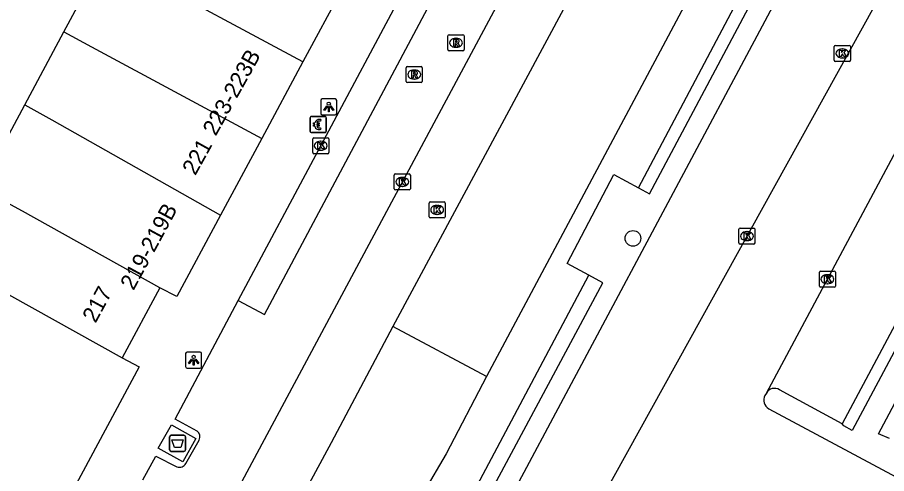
# Model space of a CAD drawing. Extents: x 159489 to 160304, y 383826 to 384530.
# Drawn here: x 159796 to 159850, y 384031.5 to 384059.8 of the extents above; entities that cross this region are included whole.
import ezdxf

# ---------------------------------------------------------------- set-up
doc = ezdxf.new("R2010")
doc.units = 0
for name, color, linetype in [('IMGEO_Afval_apart_plaats', 7, 'Continuous'), ('IMGEO_Betaalautomaat', 7, 'Continuous'), ('IMGEO_Boom', 7, 'Continuous'), ('IMGEO_Haag', 7, 'Continuous'), ('IMGEO_Kolk', 7, 'Continuous'), ('IMGEO_Lichtpunt', 7, 'Continuous'), ('IMGEO_OVBaan_gesloten', 7, 'Continuous'), ('IMGEO_Pand', 7, 'Continuous'), ('IMGEO_Pand_nummerreeks', 7, 'Continuous'), ('IMGEO_Parkeervlak_open', 7, 'Continuous'), ('IMGEO_Rijbaan_lokaal_gesloten', 7, 'Continuous'), ('IMGEO_Rijbaan_lokaal_open', 7, 'Continuous'), ('IMGEO_Rioolput', 7, 'Continuous'), ('IMGEO_Voetpad_gesloten', 7, 'Continuous'), ('IMGEO_Voetpad_open', 7, 'Continuous')]:
    doc.layers.add(name, color=color, linetype=linetype)

msp = doc.modelspace()

# ---------------------------------------------------------------- linework, layer by layer
at = {"layer": 'IMGEO_Afval_apart_plaats'}
for p, q in [((159805.424, 384032.955), (159805.424, 384033.755)), ((159805.424, 384033.755), (159805.424, 384032.955)), ((159805.524, 384033.855), (159806.314, 384033.855)), ((159806.314, 384033.855), (159805.524, 384033.855)), ((159806.414, 384033.755), (159806.414, 384032.955)), ((159806.414, 384032.955), (159806.414, 384033.755)), ((159806.314, 384032.855), (159805.524, 384032.855)), ((159805.524, 384032.855), (159806.314, 384032.855))]:
    msp.add_line(p, q, dxfattribs=at)
msp.add_lwpolyline([(159805.567, 384033.569), (159806.271, 384033.569), (159806.122, 384033.099), (159805.716, 384033.099), (159805.567, 384033.569)], dxfattribs=at)
for centre, start, end in [((159805.524, 384033.755), 90, 180), ((159805.524, 384033.755), 90, 180), ((159806.314, 384033.755), 0, 90), ((159806.314, 384033.755), 360, 90), ((159805.524, 384032.955), 180, 270), ((159805.524, 384032.955), 180, 270), ((159806.314, 384032.955), 270, 0), ((159806.314, 384032.955), 270, 0)]:
    msp.add_arc(centre, 0.1, start, end, dxfattribs=at)
at = {"layer": 'IMGEO_Betaalautomaat'}
for p, q in [((159814.162, 384052.733), (159814.162, 384053.574)), ((159814.162, 384053.574), (159814.162, 384052.733)), ((159814.237, 384053.657), (159815.078, 384053.657)), ((159815.078, 384053.657), (159814.237, 384053.657)), ((159814.824, 384053.462), (159814.807, 384053.362)), ((159815.161, 384053.583), (159815.161, 384052.742)), ((159815.161, 384052.742), (159815.161, 384053.583)), ((159814.445, 384053.121), (159814.445, 384053.189)), ((159814.566, 384053.189), (159814.566, 384053.121)), ((159814.811, 384052.956), (159814.833, 384052.869)), ((159815.087, 384052.658), (159814.246, 384052.658)), ((159814.246, 384052.658), (159815.087, 384052.658))]:
    msp.add_line(p, q, dxfattribs=at)
for points in [[(159814.445, 384053.189), (159814.376, 384053.189), (159814.376, 384053.258), (159814.455, 384053.258)], [(159814.45, 384053.052), (159814.376, 384053.052), (159814.376, 384053.121), (159814.445, 384053.121)], [(159814.577, 384053.258), (159814.724, 384053.258), (159814.724, 384053.189), (159814.566, 384053.189)], [(159814.566, 384053.121), (159814.724, 384053.121), (159814.724, 384053.052), (159814.58, 384053.052)]]:
    msp.add_lwpolyline(points, dxfattribs=at)
for centre, radius, start, end in [((159814.24, 384053.58), 0.0779, 92.4484, 184.2845), ((159814.24, 384053.58), 0.0779, 92.4484, 184.2845), ((159814.738, 384053.182), 0.293, 73.014, 165.0139), ((159814.744, 384053.195), 0.179, 69.3236, 159.5683), ((159815.084, 384053.58), 0.0779, 2.4484, 94.2845), ((159815.084, 384053.58), 0.0779, 2.4484, 94.2845), ((159814.711, 384053.107), 0.267, 191.8096, 297.0389), ((159814.744, 384053.122), 0.179, 202.7625, 291.8693), ((159814.24, 384052.736), 0.0779, 182.4484, 274.2845), ((159814.24, 384052.736), 0.0779, 182.4484, 274.2845), ((159815.084, 384052.736), 0.0779, 272.4484, 4.2845), ((159815.084, 384052.736), 0.0779, 272.4484, 4.2845)]:
    msp.add_arc(centre, radius, start, end, dxfattribs=at)
at = {"layer": 'IMGEO_Boom'}
msp.add_circle((159834.227, 384046.085), 0.489, dxfattribs=at)
at = {"layer": 'IMGEO_Haag'}
for points in [[(159834.573, 384049.218), (159855.048, 384087.89)], [(159868.118, 384073.693), (159868.262, 384073.615), (159868.311, 384073.703), (159868.832, 384073.417), (159847.849, 384034.159), (159847.33, 384034.432), (159847.224, 384034.568)], [(159850.179, 384033.662), (159849.485, 384033.948), (159870.159, 384072.714), (159870.692, 384072.419), (159870.643, 384072.32), (159870.785, 384072.243)], [(159814.597, 384012.024), (159831.482, 384043.804)]]:
    msp.add_lwpolyline(points, dxfattribs=at)
at = {"layer": 'IMGEO_Kolk'}
for p, q in [((159846.742, 384057.151), (159846.742, 384058.003)), ((159846.817, 384058.077), (159847.669, 384058.077)), ((159847.23, 384057.857), (159847.255, 384057.857)), ((159847.743, 384058.003), (159847.743, 384057.151)), ((159847.253, 384057.297), (159847.228, 384057.297)), ((159847.669, 384057.077), (159846.817, 384057.077)), ((159814.392, 384052.341), (159815.244, 384052.341)), ((159814.317, 384051.415), (159814.317, 384052.267)), ((159814.805, 384052.121), (159814.83, 384052.121)), ((159815.318, 384052.267), (159815.318, 384051.415)), ((159815.244, 384051.341), (159814.392, 384051.341)), ((159814.828, 384051.561), (159814.803, 384051.561)), ((159819.387, 384049.169), (159819.387, 384050.021)), ((159819.462, 384050.095), (159820.314, 384050.095)), ((159819.875, 384049.875), (159819.9, 384049.875)), ((159820.388, 384050.021), (159820.388, 384049.169)), ((159820.314, 384049.095), (159819.462, 384049.095)), ((159819.898, 384049.315), (159819.873, 384049.315)), ((159821.553, 384047.43), (159821.553, 384048.282)), ((159821.628, 384048.356), (159822.48, 384048.356)), ((159822.041, 384048.136), (159822.066, 384048.136)), ((159822.554, 384048.282), (159822.554, 384047.43)), ((159822.064, 384047.576), (159822.039, 384047.576)), ((159822.48, 384047.356), (159821.628, 384047.356)), ((159840.813, 384045.8), (159840.813, 384046.652)), ((159840.888, 384046.726), (159841.74, 384046.726)), ((159841.301, 384046.506), (159841.326, 384046.506)), ((159841.814, 384046.652), (159841.814, 384045.8)), ((159841.324, 384045.946), (159841.299, 384045.946)), ((159841.74, 384045.726), (159840.888, 384045.726)), ((159845.815, 384043.125), (159845.815, 384043.977)), ((159845.89, 384044.051), (159846.742, 384044.051)), ((159846.303, 384043.831), (159846.328, 384043.831)), ((159846.816, 384043.977), (159846.816, 384043.125)), ((159846.326, 384043.271), (159846.301, 384043.271)), ((159846.742, 384043.051), (159845.89, 384043.051))]:
    msp.add_line(p, q, dxfattribs=at)
for points in [[(159846.742, 384057.151), (159846.742, 384058.003)], [(159846.817, 384058.077), (159847.669, 384058.077)], [(159847.063, 384057.777), (159847.186, 384057.777), (159847.186, 384057.626), (159847.316, 384057.777), (159847.48, 384057.777), (159847.334, 384057.626), (159847.487, 384057.377), (159847.335, 384057.377), (159847.25, 384057.541), (159847.186, 384057.474), (159847.186, 384057.377), (159847.063, 384057.377), (159847.063, 384057.777)], [(159847.743, 384058.003), (159847.743, 384057.151)], [(159847.669, 384057.077), (159846.817, 384057.077)], [(159814.392, 384052.341), (159815.244, 384052.341)], [(159814.317, 384051.415), (159814.317, 384052.267)], [(159814.638, 384052.041), (159814.761, 384052.041), (159814.761, 384051.89), (159814.891, 384052.041), (159815.055, 384052.041), (159814.909, 384051.89), (159815.062, 384051.641), (159814.91, 384051.641), (159814.825, 384051.805), (159814.761, 384051.738), (159814.761, 384051.641), (159814.638, 384051.641), (159814.638, 384052.041)], [(159815.318, 384052.267), (159815.318, 384051.415)], [(159815.244, 384051.341), (159814.392, 384051.341)], [(159819.387, 384049.169), (159819.387, 384050.021)], [(159819.462, 384050.095), (159820.314, 384050.095)], [(159819.708, 384049.795), (159819.831, 384049.795), (159819.831, 384049.644), (159819.961, 384049.795), (159820.125, 384049.795), (159819.979, 384049.644), (159820.132, 384049.395), (159819.98, 384049.395), (159819.895, 384049.559), (159819.831, 384049.492), (159819.831, 384049.395), (159819.708, 384049.395), (159819.708, 384049.795)], [(159820.388, 384050.021), (159820.388, 384049.169)], [(159820.314, 384049.095), (159819.462, 384049.095)], [(159821.553, 384047.43), (159821.553, 384048.282)], [(159821.628, 384048.356), (159822.48, 384048.356)], [(159821.874, 384048.056), (159821.997, 384048.056), (159821.997, 384047.905), (159822.127, 384048.056), (159822.291, 384048.056), (159822.145, 384047.905), (159822.298, 384047.656), (159822.146, 384047.656), (159822.061, 384047.82), (159821.997, 384047.753), (159821.997, 384047.656), (159821.874, 384047.656), (159821.874, 384048.056)], [(159822.554, 384048.282), (159822.554, 384047.43)], [(159822.48, 384047.356), (159821.628, 384047.356)], [(159840.813, 384045.8), (159840.813, 384046.652)], [(159840.888, 384046.726), (159841.74, 384046.726)], [(159841.134, 384046.426), (159841.257, 384046.426), (159841.257, 384046.275), (159841.387, 384046.426), (159841.551, 384046.426), (159841.405, 384046.275), (159841.558, 384046.026), (159841.406, 384046.026), (159841.321, 384046.19), (159841.257, 384046.123), (159841.257, 384046.026), (159841.134, 384046.026), (159841.134, 384046.426)], [(159841.814, 384046.652), (159841.814, 384045.8)], [(159841.74, 384045.726), (159840.888, 384045.726)], [(159845.815, 384043.125), (159845.815, 384043.977)], [(159845.89, 384044.051), (159846.742, 384044.051)], [(159846.136, 384043.751), (159846.259, 384043.751), (159846.259, 384043.6), (159846.389, 384043.751), (159846.553, 384043.751), (159846.407, 384043.6), (159846.56, 384043.351), (159846.408, 384043.351), (159846.323, 384043.515), (159846.259, 384043.448), (159846.259, 384043.351), (159846.136, 384043.351), (159846.136, 384043.751)], [(159846.816, 384043.977), (159846.816, 384043.125)], [(159846.742, 384043.051), (159845.89, 384043.051)]]:
    msp.add_lwpolyline(points, dxfattribs=at)
for centre, start, end in [((159846.819, 384058.001), 91.552, 178.448), ((159846.819, 384058.001), 91.552, 178.448), ((159847.667, 384058.001), 1.552, 88.448), ((159847.667, 384058.001), 1.552, 88.448), ((159846.819, 384057.153), 181.552, 268.448), ((159846.819, 384057.153), 181.552, 268.448), ((159847.667, 384057.153), 271.552, 358.448), ((159847.667, 384057.153), 271.552, 358.448), ((159814.394, 384052.265), 91.552, 178.448), ((159814.394, 384052.265), 91.552, 178.448), ((159815.242, 384052.265), 1.552, 88.448), ((159815.242, 384052.265), 1.552, 88.448), ((159814.394, 384051.417), 181.552, 268.448), ((159814.394, 384051.417), 181.552, 268.448), ((159815.242, 384051.417), 271.552, 358.448), ((159815.242, 384051.417), 271.552, 358.448), ((159819.464, 384050.019), 91.552, 178.448), ((159819.464, 384050.019), 91.552, 178.448), ((159820.312, 384050.019), 1.552, 88.448), ((159820.312, 384050.019), 1.552, 88.448), ((159819.464, 384049.171), 181.552, 268.448), ((159819.464, 384049.171), 181.552, 268.448), ((159820.312, 384049.171), 271.552, 358.448), ((159820.312, 384049.171), 271.552, 358.448), ((159821.63, 384048.28), 91.552, 178.448), ((159821.63, 384048.28), 91.552, 178.448), ((159822.478, 384048.28), 1.552, 88.448), ((159822.478, 384048.28), 1.552, 88.448), ((159821.63, 384047.432), 181.552, 268.448), ((159821.63, 384047.432), 181.552, 268.448), ((159822.478, 384047.432), 271.552, 358.448), ((159822.478, 384047.432), 271.552, 358.448), ((159840.89, 384046.65), 91.552, 178.448), ((159840.89, 384046.65), 91.552, 178.448), ((159841.738, 384046.65), 1.552, 88.448), ((159841.738, 384046.65), 1.552, 88.448), ((159840.89, 384045.802), 181.552, 268.448), ((159840.89, 384045.802), 181.552, 268.448), ((159841.738, 384045.802), 271.552, 358.448), ((159841.738, 384045.802), 271.552, 358.448), ((159845.892, 384043.975), 91.552, 178.448), ((159845.892, 384043.975), 91.552, 178.448), ((159846.74, 384043.975), 1.552, 88.448), ((159846.74, 384043.975), 1.552, 88.448), ((159845.892, 384043.127), 181.552, 268.448), ((159845.892, 384043.127), 181.552, 268.448), ((159846.74, 384043.127), 271.552, 358.448), ((159846.74, 384043.127), 271.552, 358.448)]:
    msp.add_arc(centre, 0.0765, start, end, dxfattribs=at)
for centre, major_axis, ratio, start_param, end_param in [((159847.229, 384057.577), (-0.387, 0.002), 0.722429, 4.712389, 7.853982), ((159847.254, 384057.577), (-0.39, 0.002), 0.717154, 1.570796, 4.712389), ((159814.804, 384051.841), (-0.387, 0.002), 0.722429, 4.712389, 7.853982), ((159814.829, 384051.841), (-0.39, 0.002), 0.717154, 1.570796, 4.712389), ((159819.874, 384049.595), (-0.387, 0.002), 0.722429, 4.712389, 7.853982), ((159819.899, 384049.595), (-0.39, 0.002), 0.717154, 1.570796, 4.712389), ((159822.04, 384047.856), (-0.387, 0.002), 0.722429, 4.712389, 7.853982), ((159822.065, 384047.856), (-0.39, 0.002), 0.717154, 1.570796, 4.712389), ((159841.3, 384046.226), (-0.387, 0.002), 0.722429, 4.712389, 7.853982), ((159841.325, 384046.226), (-0.39, 0.002), 0.717154, 1.570796, 4.712389), ((159846.302, 384043.551), (-0.387, 0.002), 0.722429, 4.712389, 7.853982), ((159846.327, 384043.551), (-0.39, 0.002), 0.717154, 1.570796, 4.712389)]:
    msp.add_ellipse(centre, major_axis=major_axis, ratio=ratio, start_param=start_param, end_param=end_param, dxfattribs=at)
at = {"layer": 'IMGEO_Lichtpunt'}
for p, q in [((159814.816, 384054.652), (159814.816, 384053.845)), ((159814.816, 384054.652), (159814.816, 384053.845)), ((159815.718, 384054.747), (159814.91, 384054.747)), ((159815.718, 384054.747), (159814.91, 384054.747)), ((159815.812, 384053.845), (159815.812, 384054.652)), ((159815.812, 384053.845), (159815.812, 384054.652)), ((159814.91, 384053.751), (159815.718, 384053.751)), ((159814.91, 384053.751), (159815.718, 384053.751)), ((159806.418, 384038.925), (159806.418, 384038.118)), ((159806.418, 384038.925), (159806.418, 384038.118)), ((159807.32, 384039.02), (159806.512, 384039.02)), ((159807.32, 384039.02), (159806.512, 384039.02)), ((159807.414, 384038.118), (159807.414, 384038.925)), ((159807.414, 384038.118), (159807.414, 384038.925)), ((159806.512, 384038.024), (159807.32, 384038.024)), ((159806.512, 384038.024), (159807.32, 384038.024))]:
    msp.add_line(p, q, dxfattribs=at)
for points in [[(159815.19, 384054.316), (159815.229, 384054.288), (159815.041, 384054.026), (159815.003, 384054.053), (159815.19, 384054.316)], [(159815.292, 384054.268), (159815.339, 384054.268), (159815.339, 384053.946), (159815.292, 384053.946), (159815.292, 384054.268)], [(159815.402, 384054.288), (159815.44, 384054.315), (159815.627, 384054.053), (159815.588, 384054.025), (159815.402, 384054.288)], [(159806.792, 384038.589), (159806.831, 384038.561), (159806.643, 384038.299), (159806.605, 384038.326), (159806.792, 384038.589)], [(159806.894, 384038.541), (159806.941, 384038.541), (159806.941, 384038.219), (159806.894, 384038.219), (159806.894, 384038.541)], [(159807.004, 384038.561), (159807.042, 384038.588), (159807.229, 384038.326), (159807.19, 384038.298), (159807.004, 384038.561)]]:
    msp.add_lwpolyline(points, dxfattribs=at)
for centre in [(159815.315, 384054.45), (159806.917, 384038.723)]:
    msp.add_circle(centre, 0.0994, dxfattribs=at)
for centre, start, end in [((159814.91, 384054.652), 90, 180), ((159814.91, 384054.652), 90, 180), ((159815.718, 384054.652), 0, 90), ((159815.718, 384054.652), 0, 90), ((159814.91, 384053.845), 180, 270), ((159814.91, 384053.845), 180, 270), ((159815.718, 384053.845), 270, 0), ((159815.718, 384053.845), 270, 360), ((159806.512, 384038.925), 90, 180), ((159806.512, 384038.925), 90, 180), ((159807.32, 384038.925), 0, 90), ((159807.32, 384038.925), 0, 90), ((159806.512, 384038.118), 180, 270), ((159806.512, 384038.118), 180, 270), ((159807.32, 384038.118), 270, 0), ((159807.32, 384038.118), 270, 360)]:
    msp.add_arc(centre, 0.0946, start, end, dxfattribs=at)
at = {"layer": 'IMGEO_OVBaan_gesloten'}
for points in [[(159852.694, 384089.13), (159852.642, 384089.035), (159831.002, 384048.525), (159825.117, 384037.509)], [(159844.928, 384088.249), (159819.297, 384040.613)], [(159819.297, 384040.613), (159815.461, 384033.388), (159806.279, 384016.403)], [(159825.117, 384037.509), (159819.297, 384040.613)], [(159825.117, 384037.509), (159822.613, 384032.7), (159821.217, 384030.334), (159812.088, 384013.422)]]:
    msp.add_lwpolyline(points, dxfattribs=at)
at = {"layer": 'IMGEO_Pand'}
for points in [[(159798.849, 384058.909), (159801.215, 384063.308), (159802.082, 384062.843)], [(159813.711, 384057.051), (159803.121, 384062.744), (159802.928, 384062.389), (159802.082, 384062.843)], [(159816.172, 384061.629), (159813.711, 384057.051)], [(159796.419, 384054.39), (159798.849, 384058.909)], [(159798.849, 384058.909), (159800.561, 384057.988), (159811.153, 384052.293)], [(159813.711, 384057.051), (159811.153, 384052.293)], [(159794.711, 384048.642), (159793.646, 384049.235), (159796.419, 384054.39)], [(159796.419, 384054.39), (159798.091, 384053.448), (159808.594, 384047.531)], [(159811.153, 384052.293), (159808.594, 384047.531)], [(159804.812, 384043.02), (159796.285, 384047.766), (159795.323, 384048.301), (159794.711, 384048.642)], [(159808.594, 384047.531), (159805.871, 384042.465), (159804.812, 384043.02)], [(159792.356, 384044.263), (159793.941, 384043.41), (159802.47, 384038.666)], [(159804.812, 384043.02), (159802.47, 384038.666)], [(159802.47, 384038.666), (159803.527, 384038.097), (159797.928, 384027.689), (159796.313, 384024.693)]]:
    msp.add_lwpolyline(points, dxfattribs=at)
at = {"layer": 'IMGEO_Parkeervlak_open'}
for points in [[(159868.118, 384073.693), (159847.224, 384034.568)], [(159847.224, 384034.568), (159843.332, 384036.683)]]:
    msp.add_lwpolyline(points, dxfattribs=at)
msp.add_arc((159843.028, 384036.196), 0.574, 58.046, 151.49, dxfattribs=at)
at = {"layer": 'IMGEO_Rijbaan_lokaal_gesloten'}
for points in [[(159841.694, 384089.989), (159825.877, 384060.739), (159803.412, 384018.855), (159803.036, 384018.159)], [(159809.693, 384042.226), (159811.322, 384041.358), (159821.621, 384060.678), (159834.394, 384084.181), (159834.819, 384084.963), (159833.197, 384085.844)], [(159807.126, 384034.114), (159805.766, 384034.859), (159809.693, 384042.226)], [(159806.434, 384032.107), (159807.255, 384033.557)], [(159803.752, 384031.078), (159804.558, 384032.564), (159805.875, 384031.899)]]:
    msp.add_lwpolyline(points, dxfattribs=at)
for centre, radius, start, end in [((159806.863, 384033.76), 0.441, 332.6471, 53.4323), ((159806.037, 384032.318), 0.45, 248.8647, 331.955)]:
    msp.add_arc(centre, radius, start, end, dxfattribs=at)
at = {"layer": 'IMGEO_Rijbaan_lokaal_open'}
for points in [[(159860.731, 384081.261), (159820.795, 384009.203)], [(159842.524, 384036.47), (159863.733, 384076.075)], [(159842.524, 384036.47), (159842.426, 384036.331)], [(159842.676, 384035.506), (159853.238, 384029.851)]]:
    msp.add_lwpolyline(points, dxfattribs=at)
msp.add_arc((159842.966, 384036.044), 0.612, 152.0642, 241.6526, dxfattribs=at)
at = {"layer": 'IMGEO_Rioolput'}
for p, q in [((159822.725, 384057.809), (159822.725, 384058.661)), ((159822.8, 384058.735), (159823.652, 384058.735)), ((159823.213, 384058.515), (159823.238, 384058.515)), ((159823.726, 384058.661), (159823.726, 384057.809)), ((159823.652, 384057.735), (159822.8, 384057.735)), ((159823.236, 384057.955), (159823.211, 384057.955)), ((159820.13, 384055.837), (159820.13, 384056.689)), ((159820.205, 384056.763), (159821.057, 384056.763)), ((159821.131, 384056.689), (159821.131, 384055.837)), ((159820.618, 384056.543), (159820.643, 384056.543)), ((159821.057, 384055.763), (159820.205, 384055.763)), ((159820.641, 384055.983), (159820.616, 384055.983))]:
    msp.add_line(p, q, dxfattribs=at)
for points in [[(159822.725, 384057.809), (159822.725, 384058.661)], [(159822.8, 384058.735), (159823.652, 384058.735)], [(159823.314, 384058.433), (159823.062, 384058.435), (159823.062, 384058.035)], [(159823.24, 384058.354), (159823.186, 384058.354), (159823.186, 384058.273)], [(159823.186, 384058.273), (159823.238, 384058.273)], [(159823.726, 384058.661), (159823.726, 384057.809)], [(159823.652, 384057.735), (159822.8, 384057.735)], [(159823.062, 384058.035), (159823.186, 384058.035), (159823.186, 384058.197), (159823.197, 384058.197)], [(159823.244, 384058.168), (159823.315, 384058.035), (159823.455, 384058.035), (159823.39, 384058.161)], [(159820.13, 384055.837), (159820.13, 384056.689)], [(159820.205, 384056.763), (159821.057, 384056.763)], [(159821.131, 384056.689), (159821.131, 384055.837)], [(159820.719, 384056.461), (159820.467, 384056.463), (159820.467, 384056.063)], [(159820.467, 384056.063), (159820.591, 384056.063), (159820.591, 384056.225), (159820.602, 384056.225)], [(159820.645, 384056.382), (159820.591, 384056.382), (159820.591, 384056.301)], [(159820.591, 384056.301), (159820.643, 384056.301)], [(159820.649, 384056.196), (159820.72, 384056.063), (159820.86, 384056.063), (159820.795, 384056.189)], [(159821.057, 384055.763), (159820.205, 384055.763)]]:
    msp.add_lwpolyline(points, dxfattribs=at)
for centre, radius, start, end in [((159822.802, 384058.659), 0.0765, 91.552, 178.448), ((159822.802, 384058.659), 0.0765, 91.552, 178.448), ((159823.222, 384058.462), 0.19, 274.7715, 282.9687), ((159823.246, 384058.258), 0.0964, 77.0061, 93.1865), ((159823.26, 384058.315), 0.0378, 276.6634, 79.6772), ((159823.313, 384058.323), 0.109, 350.3612, 89.416), ((159823.311, 384058.323), 0.112, 277.5842, 350.9817), ((159823.65, 384058.659), 0.0765, 1.552, 88.448), ((159823.65, 384058.659), 0.0765, 1.552, 88.448), ((159822.802, 384057.811), 0.0765, 181.552, 268.448), ((159822.802, 384057.811), 0.0765, 181.552, 268.448), ((159823.196, 384058.144), 0.0533, 26.0293, 88.6989), ((159823.295, 384058.108), 0.108, 29.5134, 73.7905), ((159823.65, 384057.811), 0.0765, 271.552, 358.448), ((159823.65, 384057.811), 0.0765, 271.552, 358.448), ((159820.207, 384056.687), 0.0765, 91.552, 178.448), ((159820.207, 384056.687), 0.0765, 91.552, 178.448), ((159821.055, 384056.687), 0.0765, 1.552, 88.448), ((159821.055, 384056.687), 0.0765, 1.552, 88.448), ((159820.601, 384056.172), 0.0533, 26.0293, 88.6989), ((159820.627, 384056.49), 0.19, 274.7715, 282.9687), ((159820.651, 384056.286), 0.0964, 77.0061, 93.1865), ((159820.665, 384056.343), 0.0378, 276.6634, 79.6772), ((159820.718, 384056.351), 0.109, 350.3612, 89.416), ((159820.716, 384056.351), 0.112, 277.5842, 350.9817), ((159820.7, 384056.136), 0.108, 29.5134, 73.7905), ((159820.207, 384055.839), 0.0765, 181.552, 268.448), ((159820.207, 384055.839), 0.0765, 181.552, 268.448), ((159821.055, 384055.839), 0.0765, 271.552, 358.448), ((159821.055, 384055.839), 0.0765, 271.552, 358.448)]:
    msp.add_arc(centre, radius, start, end, dxfattribs=at)
for centre, major_axis, ratio, start_param, end_param in [((159823.212, 384058.235), (-0.387, 0.002), 0.722429, 4.712389, 7.853982), ((159823.237, 384058.235), (-0.39, 0.002), 0.717154, 1.570796, 4.712389), ((159820.617, 384056.263), (-0.387, 0.002), 0.722429, 4.712389, 7.853982), ((159820.642, 384056.263), (-0.39, 0.002), 0.717154, 1.570796, 4.712389)]:
    msp.add_ellipse(centre, major_axis=major_axis, ratio=ratio, start_param=start_param, end_param=end_param, dxfattribs=at)
at = {"layer": 'IMGEO_Voetpad_gesloten'}
msp.add_lwpolyline([(159804.716, 384033.045), (159805.535, 384034.511), (159807.054, 384033.662), (159806.235, 384032.196), (159804.716, 384033.045)], dxfattribs=at)
at = {"layer": 'IMGEO_Voetpad_open'}
for points in [[(159809.693, 384042.226), (159819.995, 384061.553), (159833.197, 384085.844)], [(159834.573, 384049.218), (159835.25, 384048.848), (159852.176, 384080.661)], [(159816.486, 384010.875), (159820.158, 384017.866), (159853.355, 384080.02)], [(159831.482, 384043.804), (159830.144, 384044.526), (159833.045, 384050.053), (159834.573, 384049.218)], [(159815.316, 384011.59), (159832.362, 384043.33), (159831.482, 384043.804)]]:
    msp.add_lwpolyline(points, dxfattribs=at)

# ---------------------------------------------------------------- texts
at = {"layer": 'IMGEO_Pand_nummerreeks'}
for s, rotation, p in [('223-223B', 60.8768, (159808.291, 384052.399)), ('221', 60.9799, (159807.021, 384049.948)), ('219-219B', 61.5758, (159803.176, 384042.808)), ('217', 61.3982, (159800.817, 384040.777))]:
    msp.add_text(s, height=1, rotation=rotation, dxfattribs=at).set_placement(p)

doc.saveas('drawing.dxf')
